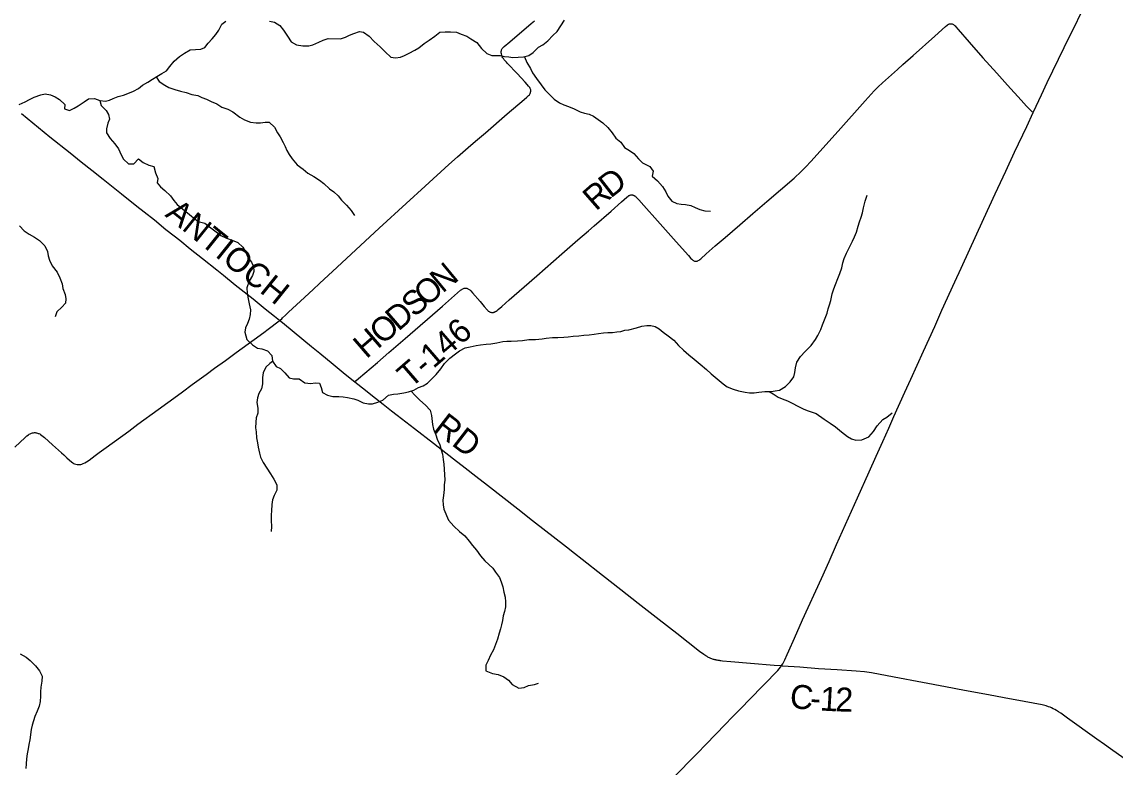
# Model space of a CAD drawing. Extents: x 1442749 to 1756758, y 235267 to 677782.
# Drawn here: x 1623834 to 1637496, y 500562 to 509882 of the extents above; entities that cross this region are included whole.
import ezdxf

# ---------------------------------------------------------------- set-up
doc = ezdxf.new("R2010")
doc.units = 0
for name, color, linetype in [('GM_X_County_Road', 7, 'Continuous'), ('GM_X_County_Road_Text', 7, 'Continuous'), ('GM_X_Major_River', 7, 'Continuous'), ('GM_X_Minor_River', 7, 'Continuous'), ('GM_X_State_Route', 7, 'Continuous'), ('GM_X_Township_Road', 7, 'Continuous'), ('GM_X_Township_Road_Text', 7, 'Continuous')]:
    doc.layers.add(name, color=color, linetype=linetype)

msp = doc.modelspace()

# ---------------------------------------------------------------- linework, layer by layer
at = {"layer": 'GM_X_County_Road'}
for points in [[(1627055, 506146), (1626993, 506196), (1626875, 506290), (1626724, 506412), (1626501, 506590), (1626353, 506709), (1626271, 506775), (1626092, 506918), (1625938, 507041), (1625807, 507146), (1625736, 507203), (1625635, 507283), (1625490, 507400), (1625362, 507503), (1625272, 507574), (1625077, 507729), (1624851, 507909), (1624707, 508024), (1624577, 508128), (1624439, 508239), (1624184, 508441), (1623973, 508613), (1623828, 508731)], [(1627993, 505378), (1627993, 505378), (1627876, 505473), (1627723, 505598), (1627556, 505735), (1627455, 505819), (1627237, 505998), (1627090, 506118), (1627055, 506146)], [(1633325, 501827), (1633237, 501834), (1632940, 501859), (1632694, 501880), (1632591, 501889), (1632570, 501892), (1632560, 501893), (1632550, 501894), (1632535, 501897), (1632523, 501899), (1632519, 501900), (1632511, 501901), (1632506, 501902), (1632495, 501905), (1632487, 501907), (1632477, 501910), (1632466, 501914), (1632458, 501916), (1632445, 501921), (1632427, 501929), (1632413, 501935), (1632406, 501939), (1632396, 501945), (1632390, 501948), (1632383, 501953), (1632357, 501970), (1632304, 502009), (1632017, 502233), (1631797, 502404), (1631536, 502608), (1631320, 502779), (1631091, 502960), (1630837, 503158), (1630740, 503235), (1630639, 503314), (1630217, 503642), (1630031, 503788), (1629651, 504085), (1629506, 504198), (1629374, 504301), (1629229, 504413), (1628980, 504607), (1628741, 504791), (1628524, 504961), (1628454, 505015), (1628351, 505096), (1628217, 505201), (1628129, 505270), (1627993, 505378)], [(1637607, 500668), (1637437, 500791), (1637362, 500844), (1637268, 500910), (1636901, 501175), (1636816, 501235), (1636790, 501253), (1636762, 501270), (1636741, 501283), (1636722, 501293), (1636702, 501303), (1636686, 501310), (1636664, 501318), (1636634, 501328), (1636585, 501340), (1636360, 501383), (1636111, 501430), (1635912, 501467), (1635615, 501522), (1635376, 501567), (1635089, 501622), (1634735, 501689), (1634451, 501741), (1634366, 501754), (1634261, 501764), (1634022, 501778), (1633790, 501793), (1633554, 501811), (1633338, 501826), (1633325, 501827)]]:
    msp.add_lwpolyline(points, dxfattribs=at)
at = {"layer": 'GM_X_Major_River'}
msp.add_lwpolyline([(1623801, 508847), (1623876, 508881), (1623930, 508909), (1623988, 508939), (1624071, 508968), (1624125, 508982), (1624193, 508970), (1624249, 508943), (1624305, 508909), (1624369, 508850), (1624368, 508796), (1624430, 508774), (1624487, 508802), (1624539, 508832), (1624611, 508881), (1624668, 508921), (1624740, 508925), (1624808, 508898)], dxfattribs=at)
at = {"layer": 'GM_X_Minor_River'}
for points in [[(1624975, 508925), (1625037, 508948), (1625102, 508967), (1625158, 508987), (1625227, 509016), (1625292, 509048), (1625342, 509091), (1625409, 509126), (1625466, 509164), (1625519, 509197), (1625583, 509237), (1625642, 509268), (1625681, 509324), (1625738, 509392), (1625805, 509447), (1625866, 509492), (1625938, 509532), (1626003, 509535), (1626071, 509540), (1626122, 509560), (1626162, 509615), (1626211, 509669), (1626256, 509725), (1626297, 509778), (1626332, 509852), (1626383, 509892)], [(1626927, 509890), (1626993, 509877), (1627059, 509836), (1627102, 509777), (1627152, 509703), (1627201, 509634), (1627265, 509593), (1627345, 509580), (1627420, 509581), (1627470, 509595), (1627547, 509628), (1627601, 509651), (1627660, 509673), (1627814, 509671), (1627877, 509692), (1627927, 509714), (1627984, 509737), (1628052, 509761), (1628103, 509754), (1628172, 509705), (1628236, 509638), (1628311, 509571), (1628373, 509506), (1628446, 509441), (1628502, 509433), (1628567, 509442), (1628617, 509460), (1628672, 509491), (1628743, 509528), (1628793, 509558), (1628862, 509611), (1628923, 509651), (1628994, 509702), (1629057, 509753), (1629125, 509757), (1629191, 509756), (1629264, 509751), (1629324, 509730), (1629394, 509704), (1629446, 509671), (1629519, 509622), (1629579, 509549), (1629644, 509486), (1629706, 509461), (1629817, 509460), (1629867, 509450), (1629919, 509443), (1629971, 509438), (1630037, 509440), (1630102, 509443), (1630170, 509460), (1630223, 509498), (1630290, 509567), (1630345, 509593), (1630407, 509644), (1630469, 509710), (1630523, 509763), (1630617, 509901)], [(1630115, 509446), (1630145, 509374), (1630190, 509298), (1630216, 509245), (1630265, 509172), (1630322, 509095), (1630370, 509033), (1630427, 508972), (1630487, 508917), (1630553, 508868), (1630605, 508844), (1630667, 508823), (1630735, 508794), (1630809, 508755), (1630867, 508738), (1630923, 508726), (1630977, 508703), (1631092, 508621), (1631156, 508559), (1631211, 508496), (1631257, 508427), (1631318, 508376), (1631366, 508312), (1631427, 508273), (1631481, 508236), (1631541, 508169), (1631590, 508118), (1631680, 508071), (1631724, 508013), (1631711, 507953), (1631778, 507892), (1631838, 507821), (1631883, 507756), (1631905, 507702), (1631956, 507641), (1632020, 507610), (1632072, 507602), (1632126, 507599), (1632195, 507584), (1632249, 507562), (1632308, 507537), (1632369, 507520), (1632441, 507513)], [(1625513, 509194), (1625548, 509135), (1625620, 509092), (1625672, 509059), (1625744, 509034), (1625818, 509014), (1625886, 508997), (1625960, 508974), (1626032, 508959), (1626084, 508934), (1626140, 508914), (1626200, 508887), (1626270, 508856), (1626334, 508817), (1626407, 508788), (1626469, 508758), (1626557, 508692), (1626615, 508658), (1626689, 508627), (1626761, 508618), (1626815, 508621), (1626876, 508629), (1626926, 508626), (1626989, 508563), (1627029, 508494), (1627060, 508442), (1627100, 508375), (1627123, 508325), (1627145, 508275), (1627174, 508222), (1627210, 508167), (1627275, 508095), (1627349, 508038), (1627408, 507991), (1627482, 507946), (1627552, 507903), (1627606, 507862), (1627679, 507793), (1627731, 507758), (1627787, 507706), (1627828, 507653), (1627892, 507588), (1627949, 507521), (1627992, 507461)], [(1624808, 508898), (1624877, 508891), (1624928, 508901), (1624975, 508925)], [(1624808, 508898), (1624823, 508834), (1624887, 508775), (1624916, 508723), (1624930, 508666), (1624907, 508613), (1624890, 508545), (1624893, 508492), (1624937, 508424), (1624994, 508357), (1625042, 508294), (1625073, 508218), (1625102, 508163), (1625166, 508108), (1625234, 508105), (1625293, 508167), (1625351, 508124), (1625419, 508091), (1625485, 508071), (1625504, 507994), (1625535, 507922), (1625523, 507870), (1625568, 507819), (1625620, 507772), (1625693, 507705), (1625731, 507649), (1625774, 507596), (1625846, 507539), (1625904, 507494), (1625955, 507451), (1626039, 507386), (1626119, 507363), (1626195, 507304), (1626262, 507255), (1626320, 507209), (1626390, 507176), (1626460, 507151), (1626534, 507122), (1626594, 507065), (1626625, 507015), (1626662, 506930), (1626704, 506877), (1626727, 506821), (1626732, 506761), (1626714, 506709), (1626675, 506641), (1626646, 506557), (1626651, 506487), (1626662, 506417), (1626675, 506354), (1626693, 506282), (1626688, 506222), (1626673, 506164), (1626652, 506108), (1626630, 506056), (1626619, 506000), (1626646, 505911), (1626715, 505842), (1626779, 505803), (1626831, 505795), (1626903, 505768), (1626957, 505711), (1626966, 505639), (1627013, 505570), (1627065, 505545), (1627119, 505493), (1627174, 505430), (1627230, 505419), (1627301, 505418), (1627370, 505368), (1627445, 505361), (1627501, 505368), (1627553, 505365), (1627575, 505309), (1627592, 505247), (1627652, 505214), (1627720, 505197), (1627796, 505198), (1627850, 505192), (1627905, 505183), (1627981, 505166), (1628033, 505151), (1628099, 505117), (1628167, 505104), (1628217, 505107), (1628284, 505125), (1628346, 505152), (1628415, 505213), (1628476, 505225), (1628532, 505230), (1628606, 505241), (1628665, 505255), (1628733, 505274), (1628792, 505309), (1628849, 505331), (1628901, 505362), (1628962, 505420), (1629013, 505471), (1629068, 505543), (1629117, 505609), (1629182, 505678)], [(1634350, 507556), (1634373, 507640), (1634396, 507716)], [(1629182, 505678), (1629253, 505732), (1629304, 505767), (1629373, 505804), (1629437, 505820), (1629512, 505833), (1629564, 505842), (1629638, 505852), (1629693, 505857), (1629771, 505866), (1629846, 505883), (1629896, 505887), (1629948, 505888), (1630027, 505893), (1630089, 505897), (1630169, 505908), (1630254, 505909), (1630334, 505918), (1630385, 505927), (1630467, 505935), (1630531, 505936), (1630608, 505937), (1630662, 505944), (1630722, 505950), (1630793, 505957), (1630857, 505964), (1630923, 505968), (1630984, 505975), (1631040, 505984), (1631101, 505994), (1631155, 505997), (1631213, 505996), (1631267, 506004), (1631318, 506009), (1631370, 506025), (1631420, 506032), (1631513, 506057), (1631580, 506075), (1631644, 506084), (1631694, 506083), (1631746, 506073), (1631798, 506042), (1631850, 506001), (1631910, 505957), (1631983, 505900), (1632041, 505833), (1632102, 505776), (1632168, 505719), (1632236, 505662), (1632311, 505601), (1632391, 505534), (1632448, 505481), (1632522, 505416), (1632597, 505355), (1632649, 505319), (1632721, 505290), (1632791, 505267), (1632871, 505250), (1632926, 505243), (1632986, 505243), (1633044, 505250), (1633117, 505259), (1633197, 505260), (1633247, 505266), (1633302, 505277), (1633375, 505322), (1633436, 505382), (1633480, 505444), (1633495, 505496), (1633502, 505556), (1633519, 505628), (1633564, 505695), (1633623, 505761), (1633698, 505836), (1633751, 505908), (1633780, 505960), (1633817, 506036), (1633840, 506094), (1633873, 506175), (1633896, 506239), (1633911, 506293), (1633927, 506345), (1633942, 506399), (1633959, 506479), (1633980, 506545), (1634003, 506599), (1634030, 506671), (1634057, 506735), (1634080, 506805), (1634094, 506869), (1634111, 506923), (1634138, 506991), (1634177, 507065), (1634212, 507138), (1634241, 507192), (1634262, 507250), (1634285, 507328), (1634301, 507382), (1634324, 507440), (1634337, 507492), (1634350, 507556)], [(1623805, 507333), (1623864, 507270), (1623924, 507228), (1623990, 507189), (1624053, 507146), (1624121, 507083), (1624154, 507010), (1624164, 506954), (1624179, 506902), (1624214, 506831), (1624276, 506752), (1624307, 506680), (1624338, 506605), (1624347, 506547), (1624373, 506474), (1624382, 506418), (1624381, 506366), (1624333, 506314), (1624272, 506257), (1624249, 506195)], [(1626968, 505635), (1626931, 505611), (1626881, 505562), (1626850, 505492), (1626839, 505436), (1626840, 505357), (1626829, 505291), (1626796, 505234), (1626778, 505182), (1626771, 505120), (1626784, 505049), (1626781, 504987), (1626763, 504929), (1626758, 504877), (1626755, 504805), (1626760, 504755), (1626768, 504682), (1626777, 504616), (1626788, 504564), (1626803, 504489), (1626817, 504437), (1626848, 504370), (1626896, 504302), (1626943, 504229), (1626982, 504162), (1627020, 504092), (1627019, 504024), (1626986, 503960), (1626967, 503904), (1626956, 503846), (1626953, 503768), (1626949, 503715), (1626950, 503645), (1626953, 503573), (1626948, 503507)], [(1628699, 505264), (1628745, 505212), (1628808, 505153), (1628876, 505090), (1628935, 505027), (1628955, 504959), (1628965, 504846), (1628979, 504788), (1629006, 504719), (1629025, 504665), (1629057, 504592), (1629072, 504530), (1629089, 504474), (1629099, 504409), (1629108, 504351), (1629111, 504289), (1629118, 504152), (1629113, 504092), (1629110, 504032), (1629101, 503958), (1629096, 503900), (1629100, 503842), (1629109, 503789), (1629164, 503652), (1629231, 503575), (1629303, 503510), (1629368, 503454), (1629424, 503387), (1629467, 503334), (1629515, 503277), (1629566, 503205), (1629618, 503142), (1629718, 503052)], [(1633173, 505260), (1633221, 505230), (1633285, 505189), (1633336, 505166), (1633400, 505144), (1633460, 505115), (1633532, 505078), (1633596, 505041), (1633648, 505021), (1633708, 505000), (1633758, 504985), (1633862, 504912), (1633935, 504863), (1634003, 504818), (1634075, 504757), (1634150, 504698), (1634202, 504667), (1634254, 504651), (1634331, 504656), (1634418, 504693), (1634475, 504761), (1634522, 504832), (1634593, 504910), (1634644, 504937), (1634710, 504991)], [(1629718, 503052), (1629751, 503002), (1629801, 502932), (1629824, 502879), (1629846, 502817), (1629857, 502749), (1629873, 502687), (1629878, 502630), (1629876, 502568), (1629865, 502510), (1629850, 502454), (1629840, 502396), (1629827, 502342), (1629815, 502290), (1629800, 502238), (1629778, 502162), (1629753, 502096), (1629726, 502027), (1629692, 501963), (1629661, 501895), (1629630, 501835), (1629634, 501767), (1629714, 501732), (1629784, 501721), (1629856, 501691), (1629915, 501650), (1629963, 501596), (1630043, 501551), (1630113, 501556), (1630167, 501582), (1630241, 501597), (1630292, 501613)], [(1623812, 501980), (1623886, 501937), (1623939, 501896), (1624005, 501828), (1624056, 501767), (1624088, 501699), (1624083, 501639), (1624072, 501561), (1624068, 501505), (1624067, 501448), (1624061, 501382), (1624050, 501326), (1624026, 501260), (1623995, 501195), (1623978, 501141), (1623964, 501085), (1623951, 501031), (1623932, 500905), (1623920, 500847), (1623911, 500791), (1623899, 500727), (1623890, 500664), (1623887, 500602), (1623885, 500546)]]:
    msp.add_lwpolyline(points, dxfattribs=at)
at = {"layer": 'GM_X_State_Route'}
msp.add_lwpolyline([(1631962, 500415), (1632275, 500738), (1632381, 500845), (1632626, 501101), (1632707, 501183), (1632810, 501288), (1633080, 501566), (1633177, 501663), (1633212, 501699), (1633237, 501724), (1633257, 501745), (1633280, 501770), (1633298, 501792), (1633313, 501811), (1633325, 501827), (1633327, 501831), (1633342, 501855), (1633355, 501879), (1633367, 501902), (1633398, 501970), (1633420, 502018), (1633490, 502174), (1633591, 502402), (1633826, 502922), (1633921, 503135), (1634016, 503347), (1634275, 503929), (1634422, 504255), (1634509, 504450), (1634592, 504635), (1634666, 504800), (1634730, 504947), (1634868, 505249), (1634943, 505412), (1635101, 505762), (1635241, 506073), (1635332, 506277), (1635491, 506630), (1635571, 506803), (1635854, 507424), (1635998, 507733), (1636129, 508016), (1636239, 508254), (1636391, 508574), (1636472, 508749), (1636475, 508756), (1636575, 508970), (1636648, 509124), (1636860, 509561), (1637196, 510247)], dxfattribs=at)
at = {"layer": 'GM_X_Township_Road'}
for points in [[(1627055, 506146), (1627067, 506157), (1627082, 506169), (1627093, 506179), (1627130, 506214), (1627168, 506250), (1627317, 506389), (1627474, 506533), (1627555, 506610), (1627776, 506816), (1628008, 507033), (1628297, 507300), (1628636, 507611), (1628872, 507828), (1629168, 508098), (1629279, 508195), (1629413, 508311), (1629504, 508391), (1629626, 508496), (1629899, 508731), (1630112, 508911), (1630145, 508940), (1630167, 508961), (1630176, 508970), (1630182, 508979), (1630187, 508988), (1630190, 508997), (1630192, 509005), (1630193, 509012), (1630193, 509021), (1630193, 509032), (1630190, 509042), (1630187, 509049), (1630180, 509060), (1630173, 509069), (1630166, 509079), (1630148, 509099), (1630123, 509126), (1630023, 509234), (1629904, 509362), (1629891, 509376), (1629862, 509408), (1629851, 509423), (1629844, 509434), (1629838, 509445), (1629833, 509456), (1629830, 509465), (1629826, 509481), (1629825, 509496), (1629825, 509505), (1629825, 509512), (1629827, 509522), (1629829, 509533), (1629833, 509542), (1629838, 509549), (1629844, 509557), (1629861, 509575), (1629884, 509594), (1629906, 509613), (1630020, 509708), (1630200, 509861), (1630239, 509896)], [(1627993, 505378), (1628009, 505393), (1628040, 505421), (1628120, 505490), (1628277, 505624), (1628421, 505749), (1628622, 505923), (1629089, 506326), (1629317, 506525), (1629331, 506536), (1629338, 506541), (1629343, 506544), (1629351, 506547), (1629360, 506550), (1629365, 506551), (1629375, 506551), (1629381, 506551), (1629387, 506551), (1629394, 506550), (1629404, 506547), (1629409, 506545), (1629417, 506540), (1629423, 506536), (1629431, 506529), (1629445, 506518), (1629467, 506494), (1629561, 506384), (1629613, 506321), (1629647, 506280), (1629656, 506272), (1629662, 506266), (1629667, 506262), (1629674, 506258), (1629679, 506256), (1629685, 506253), (1629689, 506252), (1629696, 506250), (1629703, 506249), (1629713, 506248), (1629721, 506248), (1629727, 506249), (1629731, 506250), (1629737, 506252), (1629739, 506253), (1629743, 506254), (1629746, 506256), (1629750, 506258), (1629755, 506261), (1629762, 506265), (1629774, 506274), (1629785, 506283), (1629832, 506324), (1629923, 506405), (1630110, 506569), (1630268, 506707), (1630583, 506981), (1630783, 507155), (1630914, 507270), (1630985, 507333), (1631197, 507515), (1631329, 507632), (1631394, 507689), (1631409, 507701), (1631421, 507709), (1631428, 507712), (1631431, 507714), (1631437, 507716), (1631442, 507717), (1631447, 507718), (1631452, 507718), (1631460, 507718), (1631464, 507717), (1631471, 507716), (1631474, 507715), (1631478, 507714), (1631483, 507712), (1631489, 507709), (1631491, 507708), (1631494, 507706), (1631496, 507704), (1631501, 507700), (1631508, 507694), (1631518, 507683), (1631542, 507657), (1631605, 507585), (1631778, 507392), (1632012, 507130), (1632163, 506961), (1632194, 506924), (1632205, 506913), (1632218, 506900), (1632226, 506896), (1632232, 506893), (1632241, 506890), (1632249, 506889), (1632257, 506888), (1632265, 506889), (1632274, 506891), (1632282, 506894), (1632287, 506897), (1632296, 506902), (1632305, 506909), (1632318, 506920), (1632386, 506981), (1632499, 507081), (1632621, 507185), (1632713, 507264), (1632805, 507344), (1632969, 507485), (1633145, 507637), (1633483, 507929), (1633573, 508010), (1633632, 508067), (1633695, 508134), (1634034, 508513), (1634374, 508896), (1634484, 509018), (1634534, 509069), (1634587, 509118), (1634776, 509286), (1634845, 509347), (1634972, 509461), (1635242, 509701), (1635378, 509824), (1635398, 509840), (1635405, 509846), (1635407, 509848), (1635410, 509849), (1635414, 509852), (1635418, 509854), (1635426, 509857), (1635430, 509858), (1635436, 509859), (1635440, 509859), (1635448, 509859), (1635452, 509858), (1635459, 509856), (1635466, 509853), (1635475, 509848), (1635481, 509844), (1635489, 509837), (1635496, 509831), (1635507, 509818), (1635534, 509786), (1635670, 509626), (1635843, 509433), (1636017, 509241), (1636153, 509090), (1636320, 508904), (1636388, 508829), (1636450, 508764), (1636454, 508760), (1636462, 508756), (1636472, 508749)], [(1623744, 504564), (1623874, 504684), (1623898, 504706), (1623916, 504719), (1623926, 504725), (1623938, 504732), (1623953, 504738), (1623968, 504742), (1623978, 504744), (1623990, 504745), (1623999, 504745), (1624009, 504744), (1624018, 504743), (1624030, 504739), (1624039, 504736), (1624048, 504733), (1624057, 504728), (1624067, 504721), (1624083, 504710), (1624115, 504683), (1624218, 504591), (1624328, 504492), (1624357, 504466), (1624396, 504431), (1624429, 504399), (1624453, 504380), (1624469, 504368), (1624481, 504361), (1624493, 504355), (1624509, 504349), (1624525, 504346), (1624537, 504345), (1624549, 504345), (1624562, 504346), (1624572, 504348), (1624582, 504351), (1624592, 504354), (1624601, 504357), (1624620, 504366), (1624643, 504379), (1624676, 504402), (1624748, 504459), (1624800, 504498), (1624888, 504561), (1625170, 504765), (1625283, 504849), (1625537, 505035), (1625656, 505123), (1625779, 505211), (1625842, 505257), (1625961, 505345), (1626135, 505474), (1626242, 505550), (1626377, 505648), (1626514, 505745), (1626738, 505911), (1626857, 505998), (1626913, 506038), (1627051, 506144), (1627055, 506146)]]:
    msp.add_lwpolyline(points, dxfattribs=at)

# ---------------------------------------------------------------- texts
at = {"layer": 'GM_X_County_Road_Text'}
for s, rotation, p in [('ANTIOCH', 321.1994, (1625612, 507458)), ('RD', 322.3457, (1628962, 504773)), ('C', 354.6999, (1633422, 501303)), ('1', 356.6813, (1633802, 501271)), ('2', 358.2117, (1633995, 501260)), ('-', 356.2509, (1633677, 501279))]:
    msp.add_text(s, height=300, rotation=rotation, dxfattribs=at).set_placement(p)
at = {"layer": 'GM_X_Township_Road_Text'}
for s, rotation, p in [('D', 37.997, (1631190, 507668)), ('R', 41.2024, (1631008, 507508)), ('N', 39.5285, (1629091, 506481)), ('O', 40.7744, (1628892, 506310)), ('S', 40.7832, (1628739, 506178)), ('D', 40.7846, (1628539, 506005)), ('O', 40.7846, (1628339, 505833)), ('H', 40.7846, (1628139, 505660)), ('T-146', 40.8428, (1628689, 505291))]:
    msp.add_text(s, height=300, rotation=rotation, dxfattribs=at).set_placement(p)

doc.saveas('drawing.dxf')
